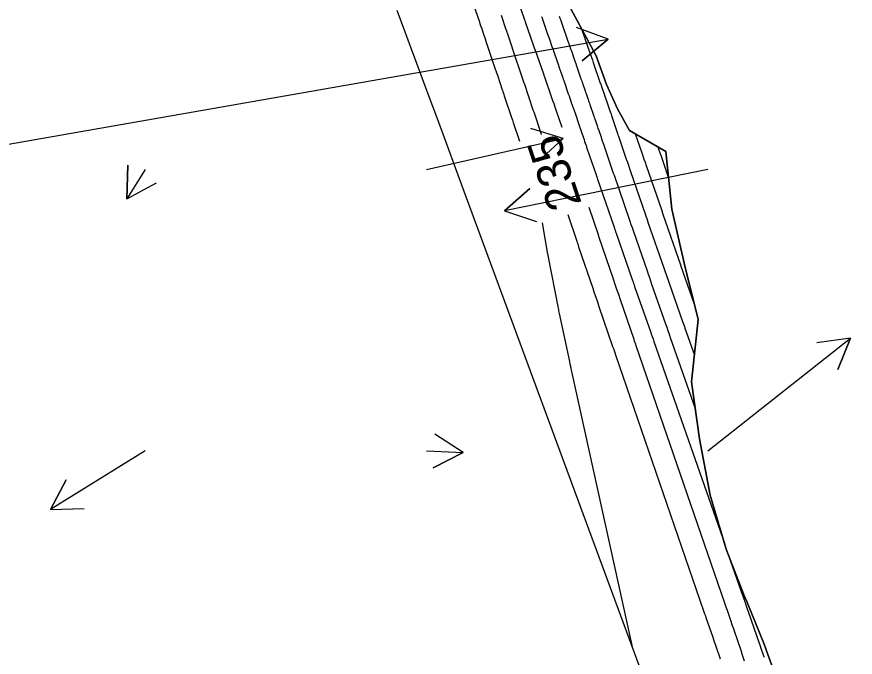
# Model space of a CAD drawing. Extents: x 954385 to 988206, y 1868364 to 1924553.
# Drawn here: x 987434.3 to 987583.3, y 1869882.2 to 1869996.1 of the extents above; entities that cross this region are included whole.
import ezdxf

# ---------------------------------------------------------------- set-up
doc = ezdxf.new("R2010")
doc.units = 0
for name, color, linetype in [('15', 7, 'Continuous'), ('24', 7, 'Continuous'), ('26', 7, 'Continuous')]:
    doc.layers.add(name, color=color, linetype=linetype)

msp = doc.modelspace()

# ---------------------------------------------------------------- linework, layer by layer
at = {"layer": '15'}
for points in [[(987523.73, 1869973.88), (987522.62, 1869977.23), (987522.54, 1869977.45), (987522.47, 1869977.68), (987522.45, 1869977.73), (987522.43, 1869977.79), (987522.41, 1869977.85), (987522.39, 1869977.9), (987521.03, 1869981.97), (987520.94, 1869982.24), (987520.79, 1869982.68), (987520.76, 1869982.77), (987520.73, 1869982.86), (987520.7, 1869982.94), (987520.67, 1869983.03), (987519.8, 1869985.63), (987519.7, 1869985.93), (987519.6, 1869986.22), (987519.57, 1869986.3), (987519.55, 1869986.37), (987519.52, 1869986.45), (987519.5, 1869986.52), (987518.05, 1869990.79), (987517.94, 1869991.11), (987517.83, 1869991.44), (987517.62, 1869992.08), (987517.56, 1869992.24), (987517.51, 1869992.41), (987517.45, 1869992.57), (987517.4, 1869992.73), (987516.91, 1869994.18), (987516.83, 1869994.41), (987516.7, 1869994.8), (987516.68, 1869994.87), (987516.65, 1869994.95), (987516.62, 1869995.03), (987516.6, 1869995.11), (987515.16, 1869999.36)], [(987531.24, 1869976.38), (987530.18, 1869979.46), (987529.99, 1869980), (987529.81, 1869980.55), (987529.62, 1869981.1), (987529.43, 1869981.65), (987528.17, 1869985.31), (987528.12, 1869985.43), (987528.07, 1869985.6), (987528.04, 1869985.67), (987527.98, 1869985.85), (987526.87, 1869989.03), (987526.85, 1869989.09), (987526.84, 1869989.14), (987526.82, 1869989.19), (987526.8, 1869989.25), (987526.69, 1869989.56), (987526.65, 1869989.67), (987524.75, 1869995.12), (987524.72, 1869995.2), (987524.62, 1869995.47), (987523.91, 1869997.53)], [(987570.31, 1869875.95), (987567.82, 1869882.73), (987567.15, 1869884.56), (987564.08, 1869892.14), (987563.68, 1869893.05), (987560.43, 1869901.46), (987557.54, 1869911.06), (987555.67, 1869921.02), (987554.23, 1869931.15), (987555.43, 1869942.25), (987553.01, 1869952.02), (987550.72, 1869961.83), (987549.7, 1869972.12), (987543.22, 1869975.82), (987541.07, 1869979.67), (987539.11, 1869984.04), (987537.3, 1869989.11), (987535.52, 1869992.44), (987532.45, 1869998.14)], [(987520.41, 1869996.31), (987520.52, 1869995.99), (987521.2, 1869993.97), (987521.22, 1869993.9), (987521.24, 1869993.84), (987521.26, 1869993.77), (987521.29, 1869993.7), (987521.42, 1869993.3), (987521.47, 1869993.17), (987523.28, 1869987.81), (987523.32, 1869987.71), (987523.98, 1869985.75), (987524.46, 1869984.31), (987524.48, 1869984.26), (987526.06, 1869979.54), (987526.15, 1869979.26), (987526.18, 1869979.19), (987526.2, 1869979.13), (987527.51, 1869975.19), (987527.52, 1869975.14)], [(987527.58, 1869996.11), (987527.63, 1869995.97), (987528.56, 1869993.29), (987528.67, 1869992.98), (987528.78, 1869992.67), (987528.89, 1869992.36), (987528.99, 1869992.05), (987529.44, 1869990.77), (987529.54, 1869990.49), (987529.64, 1869990.2), (987529.74, 1869989.92), (987529.84, 1869989.64), (987530.31, 1869988.27), (987530.42, 1869987.95), (987530.53, 1869987.63), (987530.75, 1869987), (987530.81, 1869986.84), (987530.86, 1869986.68), (987530.92, 1869986.52), (987530.97, 1869986.36), (987531.31, 1869985.4), (987531.38, 1869985.18), (987531.46, 1869984.97), (987531.53, 1869984.75), (987531.6, 1869984.54), (987532.35, 1869982.37), (987532.48, 1869981.99), (987532.62, 1869981.6), (987532.75, 1869981.22), (987532.88, 1869980.84), (987533.54, 1869978.9), (987533.6, 1869978.72), (987533.67, 1869978.54), (987533.73, 1869978.36), (987533.79, 1869978.18), (987534.04, 1869977.46), (987534.1, 1869977.28), (987534.16, 1869977.1), (987534.22, 1869976.92), (987534.28, 1869976.74), (987535.03, 1869974.53), (987535.14, 1869974.22), (987535.24, 1869973.91), (987535.45, 1869973.3), (987535.5, 1869973.15), (987535.56, 1869972.99), (987535.61, 1869972.84), (987535.66, 1869972.69), (987537.28, 1869967.94), (987537.35, 1869967.76), (987537.41, 1869967.58), (987537.47, 1869967.4), (987537.53, 1869967.22), (987540.48, 1869958.65), (987540.57, 1869958.39), (987540.66, 1869958.12), (987540.76, 1869957.86), (987540.85, 1869957.6), (987543.75, 1869949.21), (987543.85, 1869948.94), (987543.94, 1869948.67), (987544.03, 1869948.41), (987544.13, 1869948.14), (987546.93, 1869940.13), (987547.08, 1869939.68), (987547.24, 1869939.23), (987547.4, 1869938.79), (987547.55, 1869938.34), (987560.16, 1869902.35)], [(987530.73, 1869996.17), (987530.8, 1869995.97), (987530.87, 1869995.78), (987530.94, 1869995.59), (987531, 1869995.39), (987532.34, 1869991.56), (987532.39, 1869991.42), (987532.44, 1869991.27), (987532.5, 1869991.12), (987532.55, 1869990.97), (987532.75, 1869990.38), (987532.85, 1869990.09), (987532.96, 1869989.79), (987533.47, 1869988.33), (987533.57, 1869988.03), (987533.67, 1869987.74), (987533.77, 1869987.45), (987533.87, 1869987.15), (987534.6, 1869985.04), (987534.68, 1869984.8), (987534.77, 1869984.56), (987534.85, 1869984.33), (987534.93, 1869984.09), (987535.28, 1869983.09), (987535.35, 1869982.87), (987535.43, 1869982.66), (987535.5, 1869982.44), (987535.57, 1869982.22), (987535.87, 1869981.35), (987535.95, 1869981.13), (987536.02, 1869980.92), (987536.1, 1869980.7), (987536.17, 1869980.48), (987536.82, 1869978.57), (987536.9, 1869978.36), (987536.97, 1869978.14), (987537.04, 1869977.93), (987537.12, 1869977.72), (987537.41, 1869976.86), (987537.48, 1869976.65), (987537.55, 1869976.44), (987537.62, 1869976.22), (987537.7, 1869976.01), (987538.17, 1869974.63), (987538.27, 1869974.33), (987538.37, 1869974.03), (987538.47, 1869973.73), (987538.58, 1869973.43), (987539.97, 1869969.35), (987540.1, 1869968.98), (987540.22, 1869968.62), (987540.35, 1869968.26), (987540.47, 1869967.9), (987543.1, 1869960.26), (987543.29, 1869959.71), (987543.48, 1869959.16), (987543.67, 1869958.61), (987543.86, 1869958.07), (987546.35, 1869950.88), (987546.55, 1869950.3), (987546.76, 1869949.71), (987546.96, 1869949.13), (987547.16, 1869948.55), (987549.64, 1869941.47), (987549.84, 1869940.87), (987550.05, 1869940.27), (987550.26, 1869939.67), (987550.47, 1869939.07), (987554.9, 1869926.43)], [(987534.65, 1869994.06), (987535.24, 1869992.36), (987535.26, 1869992.31), (987535.29, 1869992.21), (987536.18, 1869989.66), (987536.33, 1869989.23), (987536.48, 1869988.8), (987536.63, 1869988.37), (987536.77, 1869987.94), (987538.04, 1869984.28), (987538.12, 1869984.05), (987538.2, 1869983.81), (987538.22, 1869983.76), (987538.24, 1869983.71), (987538.25, 1869983.66), (987538.27, 1869983.6), (987538.38, 1869983.29), (987538.41, 1869983.19), (987539.74, 1869979.32), (987539.76, 1869979.26), (987539.78, 1869979.19), (987539.81, 1869979.12), (987539.83, 1869979.06), (987539.94, 1869978.72), (987540.01, 1869978.52), (987541.09, 1869975.33), (987541.14, 1869975.2), (987541.18, 1869975.07), (987541.23, 1869974.94), (987541.27, 1869974.81), (987542.66, 1869970.75), (987542.85, 1869970.2), (987543.04, 1869969.66), (987543.22, 1869969.11), (987543.41, 1869968.57), (987546.01, 1869961.02), (987546.15, 1869960.61), (987546.29, 1869960.2), (987546.43, 1869959.79), (987546.57, 1869959.39), (987549.33, 1869951.45), (987549.45, 1869951.1), (987549.57, 1869950.75), (987549.69, 1869950.4), (987549.81, 1869950.06), (987552.67, 1869941.88), (987552.77, 1869941.59), (987552.87, 1869941.31), (987552.97, 1869941.02), (987553.07, 1869940.74), (987554.75, 1869935.94)], [(987554.73, 1869945.07), (987552.43, 1869951.66), (987552.41, 1869951.73), (987552.38, 1869951.79), (987552.36, 1869951.85), (987552.34, 1869951.92), (987549.21, 1869960.94), (987549.16, 1869961.09), (987549.11, 1869961.24), (987549.06, 1869961.39), (987549.01, 1869961.54), (987546.24, 1869969.57), (987546.05, 1869970.13), (987545.85, 1869970.7), (987545.66, 1869971.26), (987545.47, 1869971.82), (987544.31, 1869975.2)], [(987548.25, 1869972.95), (987548.56, 1869972.04), (987548.61, 1869971.89), (987548.67, 1869971.74), (987548.72, 1869971.59), (987548.77, 1869971.43), (987550.17, 1869967.37)], [(987563.68, 1869881.56), (987563.38, 1869882.45), (987563.21, 1869882.94), (987563.18, 1869883.03), (987563.16, 1869883.11), (987563.13, 1869883.19), (987563.1, 1869883.27), (987561.81, 1869887.04), (987561.68, 1869887.42), (987561.55, 1869887.8), (987561.42, 1869888.18), (987561.29, 1869888.56), (987560.56, 1869890.69), (987560.54, 1869890.76), (987560.52, 1869890.83), (987560.49, 1869890.89), (987560.47, 1869890.96), (987560.29, 1869891.47), (987560.16, 1869891.86), (987544.42, 1869937.58), (987544.33, 1869937.85), (987544.24, 1869938.12), (987544.14, 1869938.4), (987544.05, 1869938.67), (987541.62, 1869945.77), (987541.31, 1869946.68), (987540.99, 1869947.59), (987540.68, 1869948.5), (987540.38, 1869949.41), (987537.86, 1869956.82), (987537.82, 1869956.94), (987537.78, 1869957.06), (987537.74, 1869957.18), (987537.7, 1869957.3), (987536.06, 1869962.18)], [(987532.26, 1869960.91), (987533.86, 1869956.18), (987533.94, 1869955.92), (987534.03, 1869955.67), (987534.11, 1869955.42), (987534.19, 1869955.17), (987536.69, 1869947.83), (987536.96, 1869947.02), (987537.24, 1869946.2), (987537.52, 1869945.39), (987537.8, 1869944.58), (987540.23, 1869937.48), (987540.36, 1869937.11), (987540.48, 1869936.74), (987540.61, 1869936.37), (987540.74, 1869936), (987556.4, 1869890.48), (987556.58, 1869889.96), (987556.72, 1869889.57), (987556.74, 1869889.51), (987556.76, 1869889.44), (987556.79, 1869889.38), (987556.81, 1869889.31), (987558.01, 1869885.78), (987558.15, 1869885.38), (987558.29, 1869884.98), (987558.43, 1869884.57), (987558.57, 1869884.17), (987559.33, 1869881.92)], [(987543.82, 1869883.79), (987543.64, 1869884.61), (987543.64, 1869884.62), (987532.97, 1869933.04), (987532.88, 1869933.47), (987532.78, 1869933.9), (987532.69, 1869934.33), (987532.6, 1869934.76), (987530.78, 1869943.34), (987530.74, 1869943.56), (987530.69, 1869943.78), (987530.65, 1869944.01), (987530.6, 1869944.24), (987528.79, 1869953.6), (987528.78, 1869953.67), (987528.77, 1869953.73), (987528.75, 1869953.8), (987528.74, 1869953.87), (987527.78, 1869959.42)], [(987567.2, 1869882.16), (987567.15, 1869882.32), (987567.1, 1869882.47), (987567.05, 1869882.62), (987566.99, 1869882.77), (987566.65, 1869883.76), (987566.52, 1869884.15), (987566.49, 1869884.23), (987566.46, 1869884.31), (987566.44, 1869884.39), (987566.41, 1869884.47), (987564.39, 1869890.28), (987564.14, 1869890.98), (987563.85, 1869891.82), (987563.81, 1869891.93), (987563.78, 1869892.03), (987563.74, 1869892.13), (987563.71, 1869892.23), (987563.44, 1869893), (987560.89, 1869900.25)]]:
    msp.add_lwpolyline(points, dxfattribs=at)
at = {"layer": '24'}
for points in [[(987532.45, 1869998.14), (987535.52, 1869992.44), (987537.3, 1869989.11), (987539.11, 1869984.04), (987541.07, 1869979.67), (987543.22, 1869975.82), (987549.7, 1869972.12), (987550.72, 1869961.83), (987553.01, 1869952.02), (987555.43, 1869942.25), (987554.23, 1869931.15), (987555.67, 1869921.02), (987557.54, 1869911.06), (987560.43, 1869901.46), (987563.68, 1869893.05), (987564.08, 1869892.14), (987567.15, 1869884.56), (987567.82, 1869882.73), (987570.31, 1869875.95)], [(987610.96, 1869701.85), (987513.86, 1869964.99), (987512.38, 1869969.01), (987510.75, 1869973.42), (987508.9, 1869978.39), (987507.62, 1869981.84), (987505.43, 1869987.77), (987504.5, 1869990.27), (987501.94, 1869997.15)]]:
    msp.add_lwpolyline(points, dxfattribs=at)
at = {"layer": '26'}
for points in [[(987407.13, 1869968.93), (987539.44, 1869992.08), (987534.84, 1869988.23), (987539.44, 1869992.08), (987533.81, 1869994.14)], [(987507.13, 1869968.93), (987531.43, 1869974.39), (987527.01, 1869970.32), (987531.43, 1869974.39), (987525.7, 1869976.18)], [(987457.13, 1869968.93), (987453.9, 1869963.7), (987454.08, 1869969.7), (987453.9, 1869963.7), (987459.18, 1869966.54)], [(987557.13, 1869968.93), (987521.01, 1869961.55), (987525.5, 1869965.53), (987521.01, 1869961.55), (987526.7, 1869959.65)], [(987557.13, 1869918.93), (987582.47, 1869938.95), (987580.25, 1869933.37), (987582.47, 1869938.95), (987576.53, 1869938.08)], [(987507.13, 1869918.93), (987513.67, 1869918.63), (987508.34, 1869915.87), (987513.67, 1869918.63), (987508.61, 1869921.86)], [(987457.13, 1869918.93), (987440.31, 1869908.46), (987443.13, 1869913.75), (987440.31, 1869908.46), (987446.3, 1869908.65)]]:
    msp.add_lwpolyline(points, dxfattribs=at)

# ---------------------------------------------------------------- texts
at = {"layer": '15'}
msp.add_text('235', height=6, rotation=108.4324, dxfattribs=at).set_placement((987534.77, 1869962.88))

doc.saveas('drawing.dxf')
